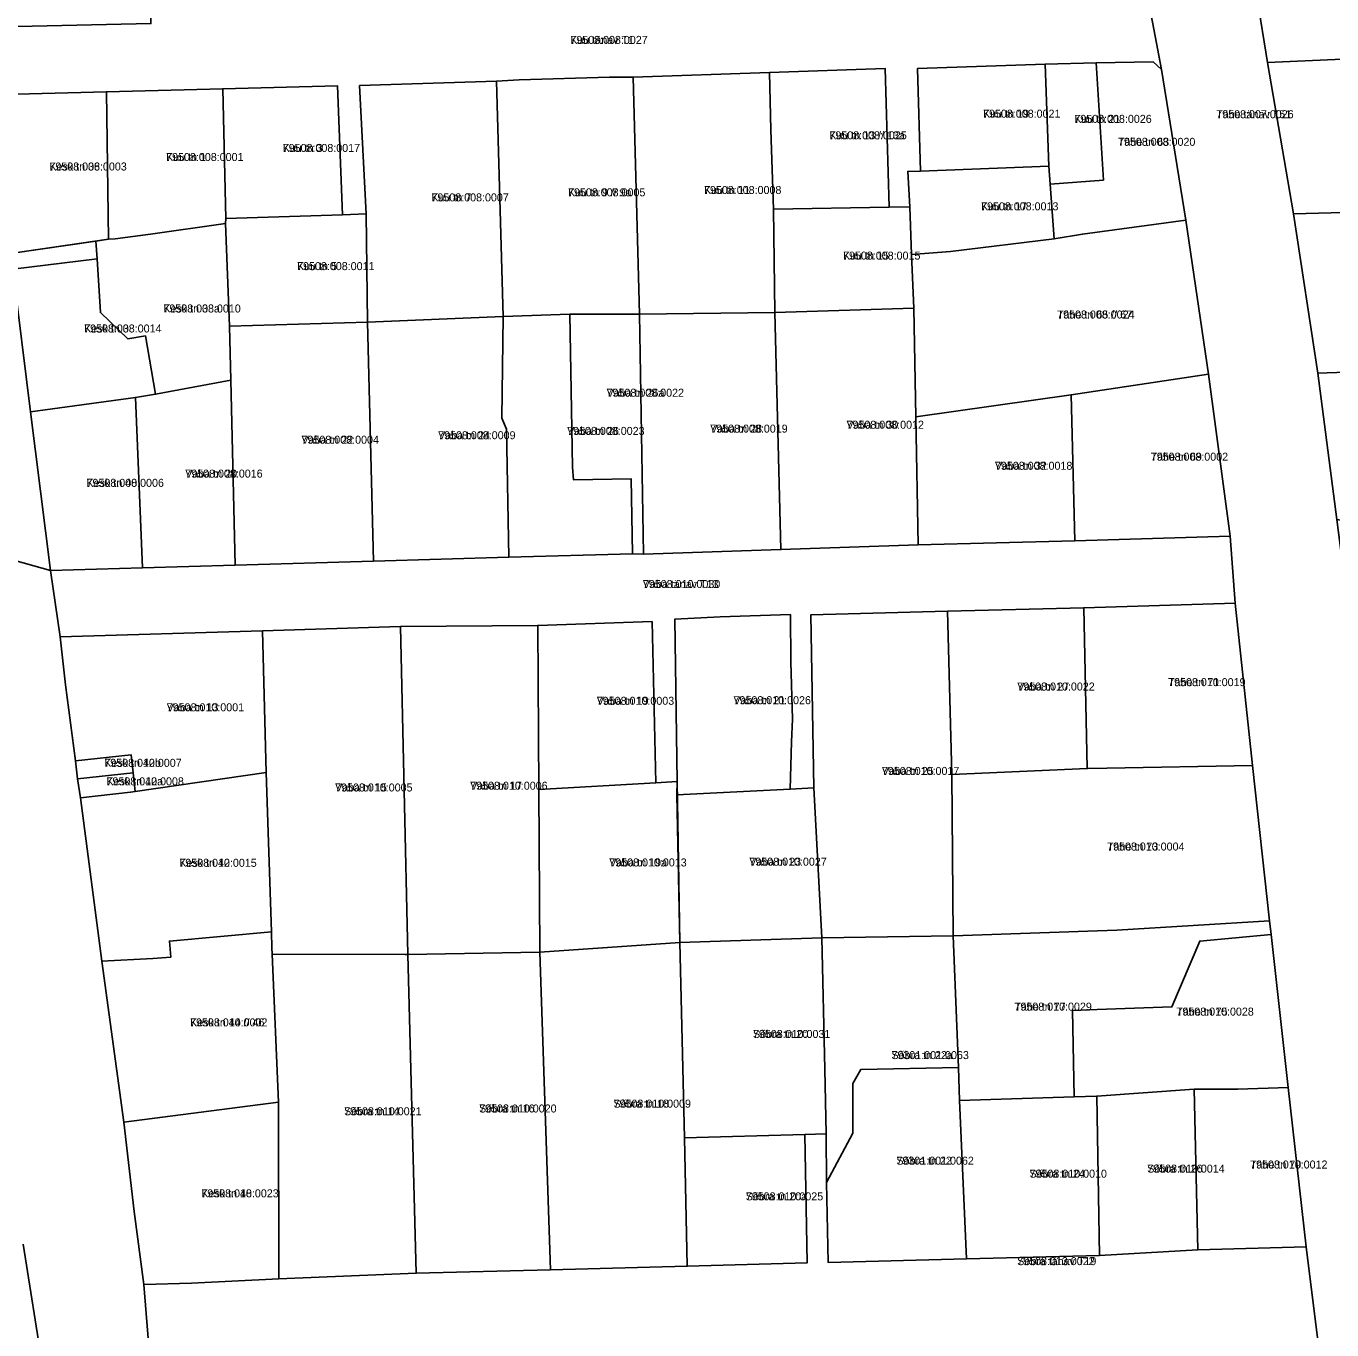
# Model space of a CAD drawing. Extents: x 643847 to 663718, y 6468443 to 6482775.
# Drawn here: x 659489.3 to 659734, y 6472589.6 to 6472833.9 of the extents above; entities that cross this region are included whole.
import ezdxf

# ---------------------------------------------------------------- set-up
doc = ezdxf.new("R2010")
doc.units = 0
for name, color, linetype in [('L_AADRESS', 7, 'Continuous'), ('PIIR', 7, 'Continuous'), ('TUNNUS', 7, 'Continuous')]:
    doc.layers.add(name, color=color, linetype=linetype)

msp = doc.modelspace()

# ---------------------------------------------------------------- linework, layer by layer
at = {"layer": 'PIIR'}
for points in [[(659480.92, 6472834.61), (659482.62, 6472821.06), (659486.38, 6472791.34), (659502.39, 6472793.65), (659502.6, 6472790.3), (659486.79, 6472788.37), (659490.11, 6472761.61), (659493.87, 6472731.89), (659472.23, 6472737.95), (659468.35, 6472769.73), (659464.34, 6472798.16), (659460.64, 6472826.93), (659455.66, 6472865.78)], [(659699.45, 6472839.66), (659702.07, 6472825.81), (659700.49, 6472827.27), (659689.83, 6472827.07), (659680.29, 6472826.79), (659656.35, 6472826), (659656.9, 6472806.75), (659654.53, 6472806.71), (659654.92, 6472800.07), (659651.03, 6472800.01), (659650.29, 6472825.96), (659628.63, 6472825.27), (659603.04, 6472824.38), (659598.61, 6472824.38), (659581.73, 6472823.87), (659577.43, 6472823.59), (659551.8, 6472822.8), (659553.02, 6472798.72), (659548.62, 6472798.58), (659547.64, 6472822.75), (659526.16, 6472822.19), (659504.35, 6472821.63), (659482.62, 6472821.06)], [(659731.79, 6472584.05), (659729.15, 6472605.12), (659725.78, 6472635.01), (659722.6, 6472663.67), (659722.31, 6472666.23), (659719.11, 6472695.37), (659715.88, 6472725.76), (659714.95, 6472738.36), (659710.85, 6472768.69), (659706.61, 6472797.55), (659702.07, 6472825.81), (659699.45, 6472839.66)], [(659720, 6472839.17), (659721.91, 6472827.14), (659726.79, 6472798.78), (659731.38, 6472768.86), (659734.92, 6472741.45), (659737.02, 6472724.87), (659741.28, 6472684.74), (659743.11, 6472665.55), (659746.14, 6472633.34), (659748.79, 6472606.82), (659751.78, 6472583.97)], [(659860.6, 6472834.56), (659827.78, 6472832.5), (659815.67, 6472832), (659805.22, 6472831.15), (659794.76, 6472830.3), (659772.57, 6472829.34), (659721.91, 6472827.14), (659720, 6472839.17)], [(659482.05, 6472833.75), (659512.71, 6472834.4)], [(659472.23, 6472737.95), (659493.87, 6472731.89), (659495.67, 6472719.47), (659496.7, 6472710.48), (659498.57, 6472696.21), (659498.95, 6472692.83), (659499.49, 6472689.27), (659503.48, 6472658.69), (659507.6, 6472628.51), (659509.58, 6472611.76), (659511.34, 6472598.06), (659513.06, 6472577.11), (659509.21, 6472544.79), (659504.21, 6472511.15), (659502.82, 6472497.4), (659497.29, 6472455.9), (659495.44, 6472442.77), (659494.28, 6472434.68), (659492.14, 6472417.48), (659489.5, 6472397.42), (659487.8, 6472384.09)], [(659488.73, 6472605.6), (659492.45, 6472582.38), (659478.13, 6472587.33)], [(659489.12, 6472559.29), (659492.45, 6472582.38), (659488.73, 6472605.6)]]:
    msp.add_lwpolyline(points, dxfattribs=at)
for points in [[(659486.22, 6472863.87), (659496.46, 6472864.8), (659506.84, 6472866.12), (659511.93, 6472866.73), (659512.71, 6472834.4), (659482.05, 6472833.75), (659480.92, 6472834.61), (659477.12, 6472862.76)], [(659721.91, 6472827.14), (659772.57, 6472829.34), (659774.91, 6472800.01), (659762.05, 6472799.68), (659761.55, 6472809.13), (659766.74, 6472809.83), (659766.07, 6472813.57), (659765.45, 6472817.08), (659764.82, 6472820.58), (659764.2, 6472824.02), (659755.24, 6472822.65), (659755.88, 6472819), (659756.51, 6472815.5), (659757.12, 6472811.99), (659757.47, 6472810.03), (659755.13, 6472809.93), (659752.05, 6472809.8), (659752.6, 6472799.44), (659726.79, 6472798.78)], [(659680.29, 6472826.79), (659680.96, 6472807.67), (659656.9, 6472806.75), (659656.35, 6472826)], [(659680.29, 6472826.79), (659689.83, 6472827.07), (659691.18, 6472805.08), (659681.2, 6472804.29), (659680.96, 6472807.67)], [(659702.07, 6472825.81), (659706.61, 6472797.55), (659687.24, 6472794.97), (659681.94, 6472794.04), (659681.2, 6472804.29), (659691.18, 6472805.08), (659689.83, 6472827.07), (659700.49, 6472827.27)], [(659578.73, 6472779.5), (659577.43, 6472823.59), (659581.73, 6472823.87), (659598.61, 6472824.38), (659603.04, 6472824.38), (659604.27, 6472779.93), (659591.18, 6472779.93)], [(659604.27, 6472779.93), (659603.04, 6472824.38), (659628.63, 6472825.27), (659628.89, 6472814.48), (659629.38, 6472799.63), (659629.64, 6472780.27)], [(659628.63, 6472825.27), (659650.29, 6472825.96), (659651.03, 6472800.01), (659629.38, 6472799.63), (659628.89, 6472814.48)], [(659482.62, 6472821.06), (659504.35, 6472821.63), (659504.73, 6472793.98), (659486.38, 6472791.34)], [(659526.16, 6472822.19), (659526.75, 6472797.87), (659526.67, 6472796.94), (659512.59, 6472794.97), (659505.98, 6472794.07), (659504.73, 6472793.98), (659504.35, 6472821.63)], [(659547.64, 6472822.75), (659548.62, 6472798.58), (659526.75, 6472797.87), (659526.16, 6472822.19)], [(659553.02, 6472798.72), (659551.8, 6472822.8), (659577.43, 6472823.59), (659578.73, 6472779.5), (659553.28, 6472778.45)], [(659656.9, 6472806.75), (659680.96, 6472807.67), (659681.2, 6472804.29), (659681.94, 6472794.04), (659662.51, 6472791.71), (659655.23, 6472791.15), (659654.92, 6472800.07), (659654.53, 6472806.71)], [(659654.92, 6472800.07), (659655.23, 6472791.15), (659655.67, 6472781.07), (659629.64, 6472780.27), (659629.38, 6472799.63), (659651.03, 6472800.01)], [(659726.79, 6472798.78), (659752.6, 6472799.44), (659755.68, 6472799.52), (659758.82, 6472799.6), (659762.05, 6472799.68), (659774.91, 6472800.01), (659777.57, 6472770.5), (659731.38, 6472768.86)], [(659503.23, 6472780.25), (659502.6, 6472790.3), (659502.39, 6472793.65), (659504.73, 6472793.98), (659505.98, 6472794.07), (659512.59, 6472794.97), (659526.67, 6472796.94), (659527.44, 6472777.67), (659527.67, 6472767.58), (659513.56, 6472764.93), (659511.68, 6472775.87), (659508.38, 6472775.34)], [(659548.62, 6472798.58), (659553.02, 6472798.72), (659553.28, 6472778.45), (659527.44, 6472777.67), (659526.67, 6472796.94), (659526.75, 6472797.87)], [(659710.85, 6472768.69), (659685.14, 6472764.82), (659656.06, 6472760.72), (659655.67, 6472781.07), (659655.23, 6472791.15), (659662.51, 6472791.71), (659681.94, 6472794.04), (659687.24, 6472794.97), (659706.61, 6472797.55)], [(659486.79, 6472788.37), (659502.6, 6472790.3), (659503.23, 6472780.25), (659508.38, 6472775.34), (659511.68, 6472775.87), (659513.56, 6472764.93), (659509.79, 6472764.34), (659490.11, 6472761.61)], [(659579.34, 6472758.4), (659578.45, 6472760.47), (659578.73, 6472779.5), (659591.18, 6472779.93), (659591.69, 6472751.25), (659591.91, 6472748.87), (659602.68, 6472749.11), (659602.94, 6472735.02), (659579.76, 6472734.42)], [(659591.69, 6472751.25), (659591.18, 6472779.93), (659604.27, 6472779.93), (659604.99, 6472734.95), (659602.94, 6472735.02), (659602.68, 6472749.11), (659591.91, 6472748.87)], [(659629.64, 6472780.27), (659630.75, 6472735.83), (659604.99, 6472734.95), (659604.27, 6472779.93)], [(659630.75, 6472735.83), (659629.64, 6472780.27), (659655.67, 6472781.07), (659656.06, 6472760.72), (659656.46, 6472736.74)], [(659554.4, 6472733.62), (659528.48, 6472732.89), (659527.67, 6472767.58), (659527.44, 6472777.67), (659553.28, 6472778.45)], [(659554.4, 6472733.62), (659553.28, 6472778.45), (659578.73, 6472779.5), (659578.45, 6472760.47), (659579.34, 6472758.4), (659579.76, 6472734.42)], [(659737.93, 6472738.98), (659736.81, 6472741.16), (659734.92, 6472741.45), (659731.38, 6472768.86), (659777.57, 6472770.5), (659780.17, 6472740.02)], [(659511.15, 6472732.42), (659509.79, 6472764.34), (659513.56, 6472764.93), (659527.67, 6472767.58), (659528.48, 6472732.89)], [(659710.85, 6472768.69), (659714.95, 6472738.36), (659685.82, 6472737.46), (659685.14, 6472764.82)], [(659490.11, 6472761.61), (659509.79, 6472764.34), (659511.15, 6472732.42), (659493.87, 6472731.89)], [(659656.46, 6472736.74), (659656.06, 6472760.72), (659685.14, 6472764.82), (659685.82, 6472737.46)], [(659495.67, 6472719.47), (659493.87, 6472731.89), (659511.15, 6472732.42), (659528.48, 6472732.89), (659554.4, 6472733.62), (659579.76, 6472734.42), (659602.94, 6472735.02), (659604.99, 6472734.95), (659630.75, 6472735.83), (659656.46, 6472736.74), (659685.82, 6472737.46), (659714.95, 6472738.36), (659715.88, 6472725.76), (659687.51, 6472724.91), (659661.95, 6472724.25), (659636.35, 6472723.57), (659636.93, 6472691.16), (659632.48, 6472690.89), (659632.76, 6472699.76), (659632.89, 6472704.01), (659632.59, 6472714.76), (659632.53, 6472723.63), (659619.35, 6472723.23), (659610.85, 6472722.76), (659611.31, 6472692.37), (659607.32, 6472692.13), (659606.61, 6472722.32), (659585.19, 6472721.62), (659559.47, 6472721.38), (659533.59, 6472720.58)], [(659610.85, 6472722.76), (659619.35, 6472723.23), (659632.53, 6472723.63), (659632.59, 6472714.76), (659632.89, 6472704.01), (659632.76, 6472699.76), (659632.48, 6472690.89), (659611.24, 6472689.87), (659611.31, 6472692.37)], [(659661.95, 6472724.25), (659662.77, 6472693.68), (659663.01, 6472663.45), (659638.43, 6472663.05), (659636.93, 6472691.16), (659636.35, 6472723.57)], [(659661.95, 6472724.25), (659687.51, 6472724.91), (659688.15, 6472694.77), (659662.77, 6472693.68)], [(659719.11, 6472695.37), (659691.8, 6472694.84), (659688.15, 6472694.77), (659687.51, 6472724.91), (659715.88, 6472725.76)], [(659559.47, 6472721.38), (659560.85, 6472659.92), (659560.34, 6472659.91), (659535.4, 6472659.99), (659535.35, 6472661.15), (659535.28, 6472664.15), (659534.27, 6472694.03), (659533.59, 6472720.58)], [(659585.19, 6472721.62), (659585.4, 6472690.83), (659585.59, 6472660.33), (659560.85, 6472659.92), (659559.47, 6472721.38)], [(659606.61, 6472722.32), (659607.32, 6472692.13), (659585.4, 6472690.83), (659585.19, 6472721.62)], [(659533.59, 6472720.58), (659534.27, 6472694.03), (659509.74, 6472690.45), (659509.35, 6472693.99), (659508.97, 6472697.37), (659498.57, 6472696.21), (659496.7, 6472710.48), (659495.67, 6472719.47)], [(659498.57, 6472696.21), (659508.97, 6472697.37), (659509.35, 6472693.99), (659498.95, 6472692.83)], [(659722.31, 6472666.23), (659693.72, 6472664.51), (659663.01, 6472663.45), (659662.77, 6472693.68), (659688.15, 6472694.77), (659691.8, 6472694.84), (659719.11, 6472695.37)], [(659498.95, 6472692.83), (659509.35, 6472693.99), (659509.74, 6472690.45), (659508.84, 6472690.35), (659499.49, 6472689.27)], [(659499.49, 6472689.27), (659508.84, 6472690.35), (659509.74, 6472690.45), (659534.27, 6472694.03), (659535.28, 6472664.15), (659516.16, 6472662.43), (659516.43, 6472659.45), (659513.04, 6472659.15), (659503.48, 6472658.69)], [(659585.4, 6472690.83), (659607.32, 6472692.13), (659611.31, 6472692.37), (659611.78, 6472662.19), (659585.59, 6472660.33)], [(659611.24, 6472689.87), (659632.48, 6472690.89), (659636.93, 6472691.16), (659638.43, 6472663.05), (659611.78, 6472662.19)], [(659722.31, 6472666.23), (659722.6, 6472663.67), (659709.22, 6472662.43), (659704.03, 6472650.11), (659689.99, 6472649.59), (659685.41, 6472649.41), (659685.73, 6472633.26), (659664.23, 6472632.56), (659664.05, 6472638.74), (659663.01, 6472663.45), (659693.72, 6472664.51)], [(659503.48, 6472658.69), (659513.04, 6472659.15), (659516.43, 6472659.45), (659516.16, 6472662.43), (659535.28, 6472664.15), (659535.35, 6472661.15), (659535.4, 6472659.99), (659536.58, 6472632.26), (659507.6, 6472628.51)], [(659639.24, 6472626.28), (659635.24, 6472626.21), (659612.69, 6472625.57), (659611.78, 6472662.19), (659638.43, 6472663.05), (659639.01, 6472638.4)], [(659644.2, 6472626.41), (659639.27, 6472617.19), (659639.24, 6472626.28), (659639.01, 6472638.4), (659638.43, 6472663.05), (659663.01, 6472663.45), (659664.05, 6472638.74), (659645.75, 6472638.39), (659644.2, 6472635.76)], [(659722.6, 6472663.67), (659725.78, 6472635.01), (659716.39, 6472634.7), (659708.19, 6472634.66), (659689.94, 6472633.39), (659685.73, 6472633.26), (659685.41, 6472649.41), (659689.99, 6472649.59), (659704.03, 6472650.11), (659709.22, 6472662.43)], [(659535.4, 6472659.99), (659560.34, 6472659.91), (659560.85, 6472659.92), (659562.42, 6472600.17), (659536.68, 6472599.15), (659536.58, 6472632.26)], [(659587.56, 6472600.82), (659562.42, 6472600.17), (659560.85, 6472659.92), (659585.59, 6472660.33)], [(659587.56, 6472600.82), (659585.59, 6472660.33), (659611.78, 6472662.19), (659612.69, 6472625.57), (659613.19, 6472601.5)], [(659665.53, 6472602.88), (659639.6, 6472602.2), (659639.27, 6472617.19), (659644.2, 6472626.41), (659644.2, 6472635.76), (659645.75, 6472638.39), (659664.05, 6472638.74), (659664.23, 6472632.56)], [(659664.23, 6472632.56), (659685.73, 6472633.26), (659689.94, 6472633.39), (659690.45, 6472603.52), (659665.53, 6472602.88)], [(659690.45, 6472603.52), (659689.94, 6472633.39), (659708.19, 6472634.66), (659708.86, 6472604.57)], [(659729.15, 6472605.12), (659708.86, 6472604.57), (659708.19, 6472634.66), (659716.39, 6472634.7), (659725.78, 6472635.01)], [(659511.34, 6472598.06), (659509.58, 6472611.76), (659507.6, 6472628.51), (659536.58, 6472632.26), (659536.68, 6472599.15), (659520.31, 6472598.33)], [(659538.75, 6472577.98), (659513.06, 6472577.11), (659511.34, 6472598.06), (659520.31, 6472598.33), (659536.68, 6472599.15), (659562.42, 6472600.17), (659587.56, 6472600.82), (659613.19, 6472601.5), (659635.65, 6472602.1), (659635.24, 6472626.21), (659639.24, 6472626.28), (659639.27, 6472617.19), (659639.6, 6472602.2), (659665.53, 6472602.88), (659690.45, 6472603.52), (659708.86, 6472604.57), (659729.15, 6472605.12), (659731.79, 6472584.05), (659692.43, 6472582.63), (659615.51, 6472580.75), (659564.68, 6472578.74), (659558.67, 6472578.5), (659549.43, 6472578.38), (659542.79, 6472578.14)], [(659635.65, 6472602.1), (659613.19, 6472601.5), (659612.69, 6472625.57), (659635.24, 6472626.21)]]:
    msp.add_lwpolyline(points, close=True, dxfattribs=at)

# ---------------------------------------------------------------- texts
at = {"layer": 'L_AADRESS'}
for s, p in [('Kuu tänav T1', (659591.29, 6472830.6)), ('Kuu tn 19', (659668.63, 6472816.77)), ('Kuu tn 21', (659685.73, 6472815.8)), ('Tähe tänav T51', (659712.33, 6472816.67)), ('Kuu tn 13 // 13a', (659639.83, 6472812.72)), ('Kuu tn 3', (659537.39, 6472810.35)), ('Tähe tn 63', (659693.91, 6472811.5)), ('Kuu tn 1', (659515.55, 6472808.65)), ('Kesk tn 36', (659493.67, 6472806.87)), ('Kuu tn 7', (659565.26, 6472801.08)), ('Kuu tn 9 // 9a', (659590.85, 6472802.03)), ('Kuu tn 11', (659616.34, 6472802.47)), ('Kuu tn 17', (659668.25, 6472799.41)), ('Kuu tn 5', (659540.09, 6472788.2)), ('Kuu tn 15', (659642.39, 6472790.17)), ('Kesk tn 38a', (659515.03, 6472780.26)), ('Tähe tn 65 // 67', (659682.51, 6472779.13)), ('Kesk tn 38', (659500.18, 6472776.51)), ('Vaba tn 26a', (659598.09, 6472764.47)), ('Vaba tn 24', (659566.52, 6472756.5)), ('Vaba tn 26', (659590.7, 6472757.31)), ('Vaba tn 28', (659617.51, 6472757.74)), ('Vaba tn 30', (659643.05, 6472758.47)), ('Vaba tn 22', (659540.92, 6472755.66)), ('Tähe tn 69', (659700.05, 6472752.48)), ('Vaba tn 20', (659519.13, 6472749.31)), ('Vaba tn 32', (659670.86, 6472750.78)), ('Kesk tn 40', (659500.63, 6472747.58)), ('Vaba tänav T13', (659604.88, 6472728.61)), ('Tähe tn 71', (659703.31, 6472710.22)), ('Vaba tn 27', (659675.05, 6472709.4)), ('Vaba tn 13', (659515.66, 6472705.51)), ('Vaba tn 19', (659596.25, 6472706.73)), ('Vaba tn 21', (659621.87, 6472706.84)), ('Kesk tn 42b', (659503.96, 6472695.1)), ('Vaba tn 25', (659649.68, 6472693.58)), ('Kesk tn 42a', (659504.37, 6472691.63)), ('Vaba tn 15', (659547.22, 6472690.48)), ('Vaba tn 17', (659572.53, 6472690.81)), ('Tähe tn 73', (659691.87, 6472679.41)), ('Kesk tn 42', (659518.02, 6472676.36)), ('Vaba tn 19a', (659598.59, 6472676.43)), ('Vaba tn 23', (659624.84, 6472676.57)), ('Tähe tn 77', (659674.51, 6472649.4)), ('Tähe tn 75', (659704.86, 6472648.47)), ('Kesk tn 44 // 46', (659520.03, 6472646.45)), ('Sõbra tn 20', (659625.51, 6472644.28)), ('Sõbra tn 22a', (659651.47, 6472640.32)), ('Sõbra tn 14', (659548.91, 6472629.79)), ('Sõbra tn 16', (659574.21, 6472630.31)), ('Sõbra tn 18', (659599.39, 6472631.22)), ('Sõbra tn 22', (659652.4, 6472620.53)), ('Tähe tn 79', (659718.67, 6472619.81)), ('Sõbra tn 24', (659677.34, 6472618.09)), ('Sõbra tn 26', (659699.4, 6472619.04)), ('Kesk tn 48', (659522.14, 6472614.41)), ('Sõbra tn 20a', (659624.17, 6472613.84)), ('Sõbra tänav T19', (659675.03, 6472601.7))]:
    msp.add_text(s, height=1.5, dxfattribs=at).set_placement(p)
at = {"layer": 'TUNNUS'}
for s, p in [('79508:008:0027', (659591.29, 6472830.6)), ('79508:008:0021', (659668.63, 6472816.77)), ('79508:008:0026', (659685.73, 6472815.8)), ('79508:007:0026', (659712.33, 6472816.67)), ('79508:008:0025', (659639.83, 6472812.72)), ('79508:008:0017', (659537.39, 6472810.35)), ('79508:008:0020', (659693.91, 6472811.5)), ('79508:008:0001', (659515.55, 6472808.65)), ('79508:008:0003', (659493.67, 6472806.87)), ('79508:008:0007', (659565.26, 6472801.08)), ('79508:008:0005', (659590.85, 6472802.03)), ('79508:008:0008', (659616.34, 6472802.47)), ('79508:008:0013', (659668.25, 6472799.41)), ('79508:008:0011', (659540.09, 6472788.2)), ('79508:008:0015', (659642.39, 6472790.17)), ('79508:008:0010', (659515.03, 6472780.26)), ('79508:008:0024', (659682.51, 6472779.13)), ('79508:008:0014', (659500.18, 6472776.51)), ('79508:008:0022', (659598.09, 6472764.47)), ('79508:008:0009', (659566.52, 6472756.5)), ('79508:008:0023', (659590.7, 6472757.31)), ('79508:008:0019', (659617.51, 6472757.74)), ('79508:008:0012', (659643.05, 6472758.47)), ('79508:008:0004', (659540.92, 6472755.66)), ('79508:008:0002', (659700.05, 6472752.48)), ('79508:008:0016', (659519.13, 6472749.31)), ('79508:008:0018', (659670.86, 6472750.78)), ('79508:008:0006', (659500.63, 6472747.58)), ('79508:010:0030', (659604.88, 6472728.61)), ('79508:010:0019', (659703.31, 6472710.22)), ('79508:010:0022', (659675.05, 6472709.4)), ('79508:010:0001', (659515.66, 6472705.51)), ('79508:010:0003', (659596.25, 6472706.73)), ('79508:010:0026', (659621.87, 6472706.84)), ('79508:010:0007', (659503.96, 6472695.1)), ('79508:010:0017', (659649.68, 6472693.58)), ('79508:010:0008', (659504.37, 6472691.63)), ('79508:010:0005', (659547.22, 6472690.48)), ('79508:010:0006', (659572.53, 6472690.81)), ('79508:010:0004', (659691.87, 6472679.41)), ('79508:010:0015', (659518.02, 6472676.36)), ('79508:010:0013', (659598.59, 6472676.43)), ('79508:010:0027', (659624.84, 6472676.57)), ('79508:010:0029', (659674.51, 6472649.4)), ('79508:010:0002', (659520.03, 6472646.45)), ('79508:010:0028', (659704.86, 6472648.47)), ('79508:010:0031', (659625.51, 6472644.28)), ('79301:001:0063', (659651.47, 6472640.32)), ('79508:010:0021', (659548.91, 6472629.79)), ('79508:010:0020', (659574.21, 6472630.31)), ('79508:010:0009', (659599.39, 6472631.22)), ('79301:001:0062', (659652.4, 6472620.53)), ('79508:010:0012', (659718.67, 6472619.81)), ('79508:010:0010', (659677.34, 6472618.09)), ('79508:010:0014', (659699.4, 6472619.04)), ('79508:010:0023', (659522.14, 6472614.41)), ('79508:010:0025', (659624.17, 6472613.84)), ('79508:013:0022', (659675.03, 6472601.7))]:
    msp.add_text(s, height=1.5, dxfattribs=at).set_placement(p)

doc.saveas('drawing.dxf')
